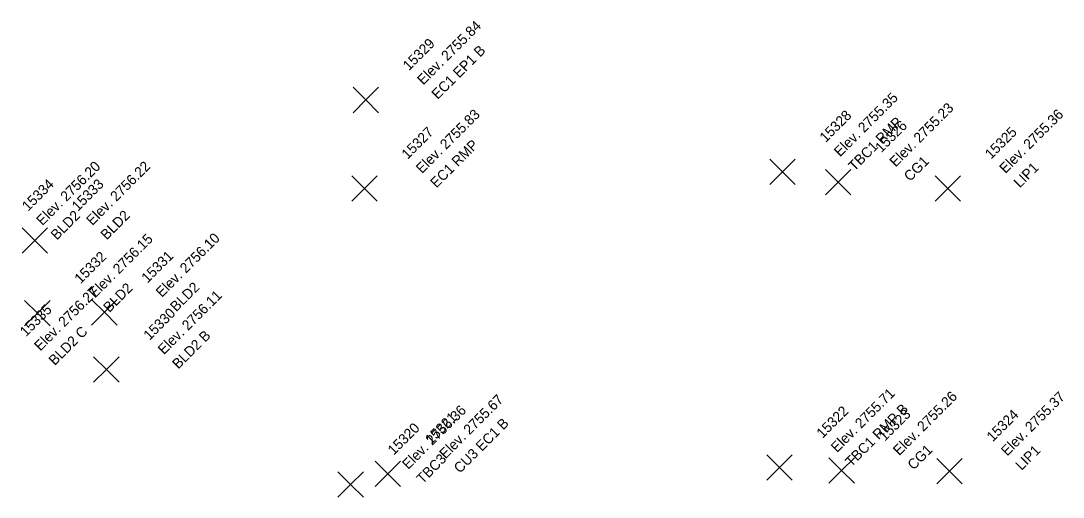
# Model space of a CAD drawing. Extents: x 2493999 to 2503109, y 700767 to 706646.
# Drawn here: x 2502251.1 to 2502263.4, y 703601.21 to 703606.83 of the extents above; entities that cross this region are included whole.
import ezdxf

# ---------------------------------------------------------------- set-up
doc = ezdxf.new("R2010")
doc.units = 0
doc.layers.add('ALG_CL_BLUE_Horiz', color=7, linetype='Continuous')
doc.layers.add('DES_SURFACE_Existing-Ground', color=7, linetype='Continuous')

msp = doc.modelspace()

# ---------------------------------------------------------------- linework, layer by layer
at = {"layer": 'ALG_CL_BLUE_Horiz'}
for points in [[(2502255.173, 703605.899), (2502255.023, 703606.049), (2502255.173, 703605.899), (2502255.023, 703605.749), (2502255.173, 703605.899), (2502255.323, 703605.749), (2502255.173, 703605.899), (2502255.323, 703606.049)], [(2502260.09, 703605.051), (2502259.94, 703605.201), (2502260.09, 703605.051), (2502259.94, 703604.901), (2502260.09, 703605.051), (2502260.24, 703604.901), (2502260.09, 703605.051), (2502260.24, 703605.201)], [(2502260.746, 703604.93), (2502260.596, 703605.08), (2502260.746, 703604.93), (2502260.596, 703604.78), (2502260.746, 703604.93), (2502260.896, 703604.78), (2502260.746, 703604.93), (2502260.896, 703605.08)], [(2502255.158, 703604.853), (2502255.008, 703605.003), (2502255.158, 703604.853), (2502255.008, 703604.703), (2502255.158, 703604.853), (2502255.308, 703604.703), (2502255.158, 703604.853), (2502255.308, 703605.003)], [(2502262.041, 703604.854), (2502261.891, 703605.004), (2502262.041, 703604.854), (2502261.891, 703604.704), (2502262.041, 703604.854), (2502262.191, 703604.704), (2502262.041, 703604.854), (2502262.191, 703605.004)], [(2502251.268, 703604.24), (2502251.118, 703604.39), (2502251.268, 703604.24), (2502251.118, 703604.09), (2502251.268, 703604.24), (2502251.418, 703604.09), (2502251.268, 703604.24), (2502251.418, 703604.39)], [(2502251.299, 703603.383), (2502251.149, 703603.533), (2502251.299, 703603.383), (2502251.149, 703603.233), (2502251.299, 703603.383), (2502251.449, 703603.233), (2502251.299, 703603.383), (2502251.449, 703603.533)], [(2502252.089, 703603.392), (2502251.939, 703603.542), (2502252.089, 703603.392), (2502251.939, 703603.242), (2502252.089, 703603.392), (2502252.239, 703603.242), (2502252.089, 703603.392), (2502252.239, 703603.542)], [(2502252.113, 703602.716), (2502251.963, 703602.866), (2502252.113, 703602.716), (2502251.963, 703602.566), (2502252.113, 703602.716), (2502252.263, 703602.566), (2502252.113, 703602.716), (2502252.263, 703602.866)], [(2502255.435, 703601.485), (2502255.285, 703601.635), (2502255.435, 703601.485), (2502255.285, 703601.335), (2502255.435, 703601.485), (2502255.585, 703601.335), (2502255.435, 703601.485), (2502255.585, 703601.635)], [(2502260.054, 703601.56), (2502259.904, 703601.71), (2502260.054, 703601.56), (2502259.904, 703601.41), (2502260.054, 703601.56), (2502260.204, 703601.41), (2502260.054, 703601.56), (2502260.204, 703601.71)], [(2502260.788, 703601.524), (2502260.638, 703601.674), (2502260.788, 703601.524), (2502260.638, 703601.374), (2502260.788, 703601.524), (2502260.938, 703601.374), (2502260.788, 703601.524), (2502260.938, 703601.674)], [(2502262.061, 703601.518), (2502261.911, 703601.668), (2502262.061, 703601.518), (2502261.911, 703601.368), (2502262.061, 703601.518), (2502262.211, 703601.368), (2502262.061, 703601.518), (2502262.211, 703601.668)], [(2502254.995, 703601.36), (2502254.845, 703601.51), (2502254.995, 703601.36), (2502254.845, 703601.21), (2502254.995, 703601.36), (2502255.145, 703601.21), (2502254.995, 703601.36), (2502255.145, 703601.51)]]:
    msp.add_lwpolyline(points, dxfattribs=at)

# ---------------------------------------------------------------- texts
at = {"layer": 'DES_SURFACE_Existing-Ground'}
for s, p in [('Elev. 2755.84', (2502255.852, 703606.069)), ('15329', (2502255.682, 703606.238)), ('EC1 EP1 B', (2502256.022, 703605.899)), ('Elev. 2755.35', (2502260.769, 703605.221)), ('Elev. 2755.23', (2502261.425, 703605.1)), ('Elev. 2755.83', (2502255.837, 703605.023)), ('15328', (2502260.599, 703605.39)), ('TBC1 RMP', (2502260.939, 703605.051)), ('Elev. 2755.36', (2502262.72, 703605.024)), ('15327', (2502255.667, 703605.192)), ('15326', (2502261.255, 703605.269)), ('15325', (2502262.55, 703605.193)), ('EC1 RMP', (2502256.007, 703604.853)), ('CG1', (2502261.595, 703604.93)), ('Elev. 2756.20', (2502251.359, 703604.409)), ('Elev. 2756.22', (2502251.947, 703604.41)), ('LIP1', (2502262.89, 703604.854)), ('15334', (2502251.189, 703604.578)), ('15333', (2502251.777, 703604.579)), ('BLD2', (2502251.529, 703604.239)), ('BLD2', (2502252.117, 703604.24)), ('Elev. 2756.10', (2502252.768, 703603.562)), ('Elev. 2756.15', (2502251.978, 703603.553)), ('15332', (2502251.808, 703603.722)), ('15331', (2502252.598, 703603.731)), ('BLD2', (2502252.148, 703603.383)), ('BLD2', (2502252.938, 703603.392)), ('Elev. 2756.27', (2502251.334, 703602.928)), ('Elev. 2756.11', (2502252.792, 703602.886)), ('15335', (2502251.164, 703603.097)), ('15330', (2502252.622, 703603.055)), ('BLD2 C', (2502251.504, 703602.758)), ('BLD2 B', (2502252.962, 703602.716)), ('Elev. 2755.71', (2502260.733, 703601.73)), ('Elev. 2755.67', (2502256.114, 703601.655)), ('Elev. 2755.26', (2502261.467, 703601.694)), ('Elev. 2755.37', (2502262.74, 703601.688)), ('Elev. 2756.36', (2502255.674, 703601.53)), ('15322', (2502260.563, 703601.899)), ('TBC1 RMP B', (2502260.903, 703601.56)), ('15323', (2502261.297, 703601.863)), ('15324', (2502262.57, 703601.857)), ('15321', (2502255.944, 703601.824)), ('CU3 EC1 B', (2502256.284, 703601.485)), ('15320', (2502255.504, 703601.699)), ('CG1', (2502261.637, 703601.524)), ('LIP1', (2502262.91, 703601.518)), ('TBC3', (2502255.844, 703601.36))]:
    msp.add_text(s, height=0.12, rotation=45, dxfattribs=at).set_placement(p)

doc.saveas('drawing.dxf')
